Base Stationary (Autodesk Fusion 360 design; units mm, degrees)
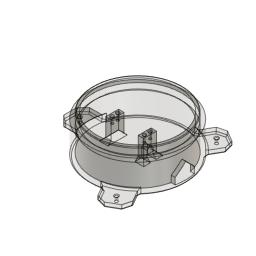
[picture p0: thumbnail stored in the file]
sketch "Sketch1" plane through (0, 0, 0) normal (0, 0, 1) x axis (1, 0, 0)
  line L1 (75, 0) -> (0, 0)
  line L2 (75, 50) -> (75, 0)
  line L3 (69, 50) -> (75, 50)
  line L4 (69, 60) -> (69, 50)
  line L5 (64, 60) -> (69, 60)
  line L6 (64, 45) -> (64, 60)
  line L7 (69, 40) -> (64, 45)
  line L8 (69, 5) -> (69, 40)
  line L9 (0, 5) -> (69, 5)
  line L10 (0, 0) -> (0, 5)
  point P1 (0, 0)
  point P2 (0, 0)
  point P12 (0, 0)
  point P5 (69, 50)
  point P6 (69, 60)
  point P3 (75, 0)
  point P4 (75, 50)
  point P8 (64, 45)
  point P9 (69, 40)
  coincident P1 P2
  horizontal L1
  perpendicular L1 L2
  perpendicular L2 L3
  perpendicular L3 L4
  perpendicular L4 L5
  perpendicular L5 L6
  perpendicular L5 L8
  perpendicular L6 L9
  coincident P1 P12
  perpendicular L1 L10
  dimension "d3" distance L1 L9 = 5
  dimension "d4" distance L4 L6 = 5
  dimension "d7" distance L2 L8 = 6
  dimension "d8" distance P5 P6 = 10
  dimension "d10" angle L6 L7 = 135
  dimension "d11" distance L2 L10 = 75
  dimension "d12" distance P3 P4 = 50
  dimension "d13" distance L3 P8 = 5
  dimension "d14" distance P8 P9 = 5
revolve "Revolve1" sketch "Sketch1" AlongAngle 360
chamfer "Chamfer1" distance 1
move "Move1" RotateAngle 90
work_plane "WorkPlane1" AlongDistance 0
sketch "Sketch2" plane through (0, 0, 0) normal (1, 0, 0) x axis (0, 1, 0)
  line L1 (69, 5) -> (-69, 5)
  line L2 (69, 40) -> (-69, 40)
  line L3 (0, 40) -> (0, 5)
  line L4 (15, 5) -> (0, 5)
  line L5 (15, 15) -> (15, 5)
  line L6 (0, 15) -> (15, 15)
  line L7 (0, 5) -> (0, 15)
  line L8 (-69, 5) -> (69, 5)
  line L9 (-15, 5) -> (0, 5)
  line L10 (0, 15) -> (-15, 15)
  line L11 (0, 40) -> (0, 5)
  line L12 (0, 5) -> (0, 15)
  line L13 (-15, 15) -> (-15, 5)
  line L14 (0, 30) -> (15, 15)
  line L15 (36.2132, 15) -> (15, 15)
  line L16 (-15, 15) -> (0, 30)
  point P6 (0, 5)
  point P7 (0, 40)
  point P2 (-69, 5)
  point P15 (69, 5)
  point P3 (69, 5)
  point P16 (-69, 5)
  point P12 (0, 5)
  point P17 (0, 40)
  point P8 (15, 5)
  point P13 (-15, 5)
  point P9 (15, 15)
  point P11 (-15, 15)
  point P10 (0, 15)
  point P14 (0, 15)
  point P18 (0, 30)
  midpoint L1 P6
  midpoint L2 P7
  horizontal L4
  vertical L5
  horizontal L6
  vertical L7
  symmetric P2 L3 P15
  symmetric P3 L3 P16
  symmetric P6 L3 P12
  symmetric P7 L3 P17
  symmetric L3 P8 P13
  symmetric L3 P9 P11
  symmetric L3 P10 P14
  horizontal L15
  coincident L3 P18
  dimension "d19" distance P6 P8 = 15
  dimension "d20" distance P6 P10 = 10
  dimension "d50" angle L14 L15 = 135
extrude "Extrude1" cut sketch "Sketch2" profile of L4 L5 L6 L7 L9 L10 L12 L13 L14 L16 to an object
sketch "Sketch3" plane through (0, 0, 5) normal (0, 0, 1) x axis (-1, 0, 0)
  line L1 (-73.4847, 15) -> (-67.3498, 15)
  line L2 (-67.3498, -15) -> (-73.4847, -15)
  line L3 (-16.65, -5.9852) -> (-16.65, -9.4)
  line L4 (24.1422, 10) -> (0, 10)
  line L5 (-16.65, -9.4) -> (-16.65, -5.9852)
  curve K1 (36.95, 5.9852) -> (36.35, 6.456)
  line L6 (-9.4, -10) -> (0, -10)
  line L7 (0, -10) -> (24.1422, -10)
  line L8 (36.95, 3.0148) -> (36.95, -3.0148)
  line L9 (36.35, -10) -> (29.7, -10)
  line L10 (24.1422, -10) -> (29.7, -10)
  line L11 (29.7, 10) -> (24.1422, 10)
  line L12 (36.35, 10) -> (29.7, 10)
  line L13 (-9.4, 10) -> (29.7, 10)
  curve K2 (36.95, -5.9852) -> (36.35, -6.456)
  line L14 (29.7, -10) -> (-9.4, -10)
  line L15 (36.95, -9.4) -> (36.95, -5.9852)
  line L16 (36.95, 5.9852) -> (36.95, 9.4)
  line L17 (-16.05, 10) -> (-9.4, 10)
  line L18 (36.95, 9.4) -> (36.95, 5.9852)
  curve K3 (-16.05, -2.544) -> (-16.65, -3.0148)
  curve K4 (-16.05, 2.544) -> (-16.65, 3.0148)
  line L19 (-16.65, 3.0148) -> (-16.65, -3.0148)
  line L20 (-9.4, 10) -> (-16.05, 10)
  line L21 (-16.65, -3.0148) -> (-16.65, 3.0148)
  line L22 (-16.65, 5.9852) -> (-16.65, 9.4)
  curve K5 (36.35, -2.544) -> (36.95, -3.0148)
  curve K6 (-16.65, -3.0148) -> (-16.05, -2.544)
  curve K7 (36.95, -3.0148) -> (36.35, -2.544)
  curve K8 (36.35, -6.456) -> (36.95, -5.9852)
  curve K9 (-16.05, -6.456) -> (-16.65, -5.9852)
  line L23 (29.7, 10) -> (36.35, 10)
  line L24 (-16.05, -10) -> (-9.4, -10)
  line L25 (36.95, -5.9852) -> (36.95, -9.4)
  curve K10 (-16.05, 6.456) -> (-16.65, 5.9852)
  curve K11 (36.95, 3.0148) -> (36.35, 2.544)
  curve K12 (-16.65, -5.9852) -> (-16.05, -6.456)
  curve K13 (-16.65, 3.0148) -> (-16.05, 2.544)
  line L26 (0, 10) -> (-9.4, 10)
  line L27 (-16.65, 9.4) -> (-16.65, 5.9852)
  curve K14 (36.35, 6.456) -> (36.95, 5.9852)
  curve K15 (-16.65, 5.9852) -> (-16.05, 6.456)
  line L28 (36.95, -3.0148) -> (36.95, 3.0148)
  line L29 (-9.4, -10) -> (-16.05, -10)
  curve K16 (36.35, 2.544) -> (36.95, 3.0148)
  line L30 (29.7, -10) -> (36.35, -10)
  line L31 (-19.4, -10) -> (-9.4, -10)
  line L32 (-19.4, 10) -> (-19.4, -10)
  line L33 (-9.4, 10) -> (-19.4, 10)
  line L34 (-9.4, -10) -> (-9.4, 10)
  line L35 (39.7, -10) -> (29.7, -10)
  line L36 (39.7, 10) -> (39.7, -10)
  line L37 (29.7, 10) -> (39.7, 10)
  line L38 (29.7, -10) -> (29.7, 10)
  line L39 (31.2, -10) -> (31.2, 10)
  line L40 (-10.9, -10) -> (-10.9, 10)
  arc A1 centre (0, 0) radius 69 clockwise from (-67.3498, 15) to (-67.3498, -15)
  arc A2 centre (0, 0) radius 75 clockwise from (-73.4847, -15) to (-73.4847, 15)
  arc A3 centre (35.3, 4.5) radius 2.22 clockwise from (36.35, 2.544) to (36.35, 6.456)
  arc A4 centre (35.3, 4.5) radius 2.22 clockwise from (36.35, 2.544) to (36.35, 6.456)
  circle C1 centre (0, 0) radius 1.3
  circle C2 centre (0, 0) radius 3.292
  arc A5 centre (35.3, -4.5) radius 2.22 clockwise from (36.35, -6.456) to (36.35, -2.544)
  arc A6 centre (-15, 4.5) radius 2.22 clockwise from (-16.05, 6.456) to (-16.05, 2.544)
  arc A7 centre (-15, 4.5) radius 2.22 clockwise from (-16.05, 6.456) to (-16.05, 2.544)
  arc A8 centre (35.3, -4.5) radius 2.22 clockwise from (36.35, -6.456) to (36.35, -2.544)
  arc A9 centre (-15, -4.5) radius 2.22 clockwise from (-16.05, -2.544) to (-16.05, -6.456)
  arc A10 centre (-15, -4.5) radius 2.22 clockwise from (-16.05, -2.544) to (-16.05, -6.456)
  point P11 (-9.4, -10)
  point P77 (-9.4, -10)
  point P13 (29.7, -10)
  point P81 (29.7, -10)
  point P78 (-19.4, -10)
  point P80 (-9.4, 10)
  point P82 (39.7, -10)
  horizontal L31
  vertical L32
  horizontal L33
  vertical L34
  coincident P11 P77
  horizontal L35
  vertical L36
  horizontal L37
  vertical L38
  coincident P13 P81
  dimension "d31" distance P77 P78 = 10
  dimension "d32" distance P77 P80 = 20
  dimension "d33" distance P81 P82 = 10
  dimension "d34" = -1.5
  dimension "d35" = 1.5
extrude "Extrude2" add sketch "Sketch3" profile of L31 L32 L33 L35 L36 L37 L39 L40 along normal blind 33
sketch "Sketch4" plane through (0, 0, 38) normal (0, 0, 1) x axis (-1, 0, 0)
  line L1 (31.2, -10) -> (31.2, 10)
  line L2 (39.7, -10) -> (31.2, -10)
  line L3 (39.7, 10) -> (39.7, -10)
  line L4 (31.2, 10) -> (39.7, 10)
  circle C1 centre (-15, -4.5) radius 1.85
  circle C2 centre (-15, 4.5) radius 1.85
  circle C3 centre (35.3, 4.5) radius 1.85
  circle C4 centre (35.3, -4.5) radius 1.85
  point P8 (-15, -4.5)
  point P10 (-15, -4.5)
  point P9 (-15, 4.5)
  point P11 (-15, 4.5)
  point P7 (35.3, 4.5)
  point P12 (35.3, 4.5)
  point P6 (35.3, -4.5)
  point P13 (35.3, -4.5)
  coincident P8 P10
  coincident P9 P11
  coincident P7 P12
  coincident P6 P13
  dimension "d38" diameter C1 = 3.7
  dimension "d39" diameter C4 = 3.7 (= "d38")
  dimension "d40" diameter C3 = 3.7 (= "d38")
  dimension "d41" diameter C2 = 3.7 (= "d38")
extrude "Extrude3" cut sketch "Sketch4" profile of C1 C2 C3 C4 against normal blind 10
chamfer "Chamfer2" distance 5
sketch "Sketch5" plane through (10.9, 0, 0) normal (-1, 0, 0) x axis (0, -1, 0)
  line L1 (15, 5) -> (-15, 5)
  line L2 (10, 10) -> (15, 5)
  line L3 (10, 38) -> (10, 10)
  line L4 (-10, 38) -> (10, 38)
  line L5 (-10, 10) -> (-10, 38)
  line L6 (-15, 5) -> (-10, 10)
  line L7 (0, 38) -> (0, 5)
  line L8 (4.5, 5) -> (0, 5)
  line L9 (4.5, 19) -> (4.5, 5)
  line L10 (0, 19) -> (4.5, 19)
  line L11 (0, 5) -> (0, 19)
  line L12 (0, 19) -> (-4.5, 19)
  line L13 (-4.5, 19) -> (-4.5, 5)
  line L14 (0, 23.5) -> (4.5, 19)
  line L15 (10.864, 19) -> (4.5, 19)
  line L16 (-4.5, 19) -> (0, 23.5)
  point P8 (0, 5)
  point P9 (0, 38)
  point P10 (4.5, 5)
  point P15 (-4.5, 5)
  point P11 (4.5, 19)
  point P13 (-4.5, 19)
  point P12 (0, 19)
  point P14 (0, 19)
  point P16 (0, 23.5)
  midpoint L1 P8
  midpoint L4 P9
  horizontal L8
  vertical L9
  horizontal L10
  vertical L11
  symmetric P10 L11 P15
  symmetric P11 L11 P13
  symmetric P12 L11 P14
  horizontal L15
  coincident L7 P16
  dimension "d45" distance P8 P10 = 4.5
  dimension "d46" distance P8 P12 = 14
  dimension "d47" angle L14 L15 = 135
extrude "Extrude4" cut sketch "Sketch5" profile of L1 L7 L8 L9 L10 L11 L12 L13 L14 L16 against normal blind 14
sketch "Sketch6" plane through (0, 0, 0) normal (0, 0, -1) x axis (1, 0, 0)
  line L1 (-100, 0) -> (0, 0)
  line L2 (-105, 0) -> (-75, 0)
  line L3 (-105, 20) -> (-105, 0)
  line L4 (-72.2842, 20) -> (-105, 20)
  line L5 (-105, -20) -> (-105, 0)
  line L6 (-105, 0) -> (-75, 0)
  line L7 (-72.2842, -20) -> (-105, -20)
  circle C1 centre (0, 0) radius 75
  circle C2 centre (-90, 0) radius 2.25
  point P1 (0, 0)
  point P3 (0, 0)
  point P5 (-75, 0)
  point P8 (-72.2842, 20)
  point P12 (-75, 0)
  point P6 (-105, 0)
  point P11 (-105, 0)
  point P7 (-105, 20)
  point P10 (-105, -20)
  point P9 (-72.2842, -20)
  point P13 (-90, 0)
  coincident P1 P3
  horizontal L1
  coincident C1 P5
  coincident L1 P5
  parallel L1 L2
  perpendicular L2 L3
  coincident C1 P8
  perpendicular L3 L4
  symmetric L1 P5 P12
  symmetric L1 P6 P11
  symmetric L1 P7 P10
  symmetric L1 P8 P9
  midpoint L6 P13
  dimension "d51" distance P5 P6 = 30
  dimension "d52" distance P6 P7 = 20
  dimension "d55" diameter C2 = 4.5
extrude "Extrude5" add sketch "Sketch6" profile of C1 L2 L3 L4 L5 L6 L7 C2 against normal blind 7.5
chamfer "Chamfer3" distance 3
circular_pattern "C-Pattern1" TotalAngle 360
chamfer "Chamfer4" distance 10
chamfer "Chamfer5" distance 1
chamfer "Chamfer6" sketch "Sketch6" distance 2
